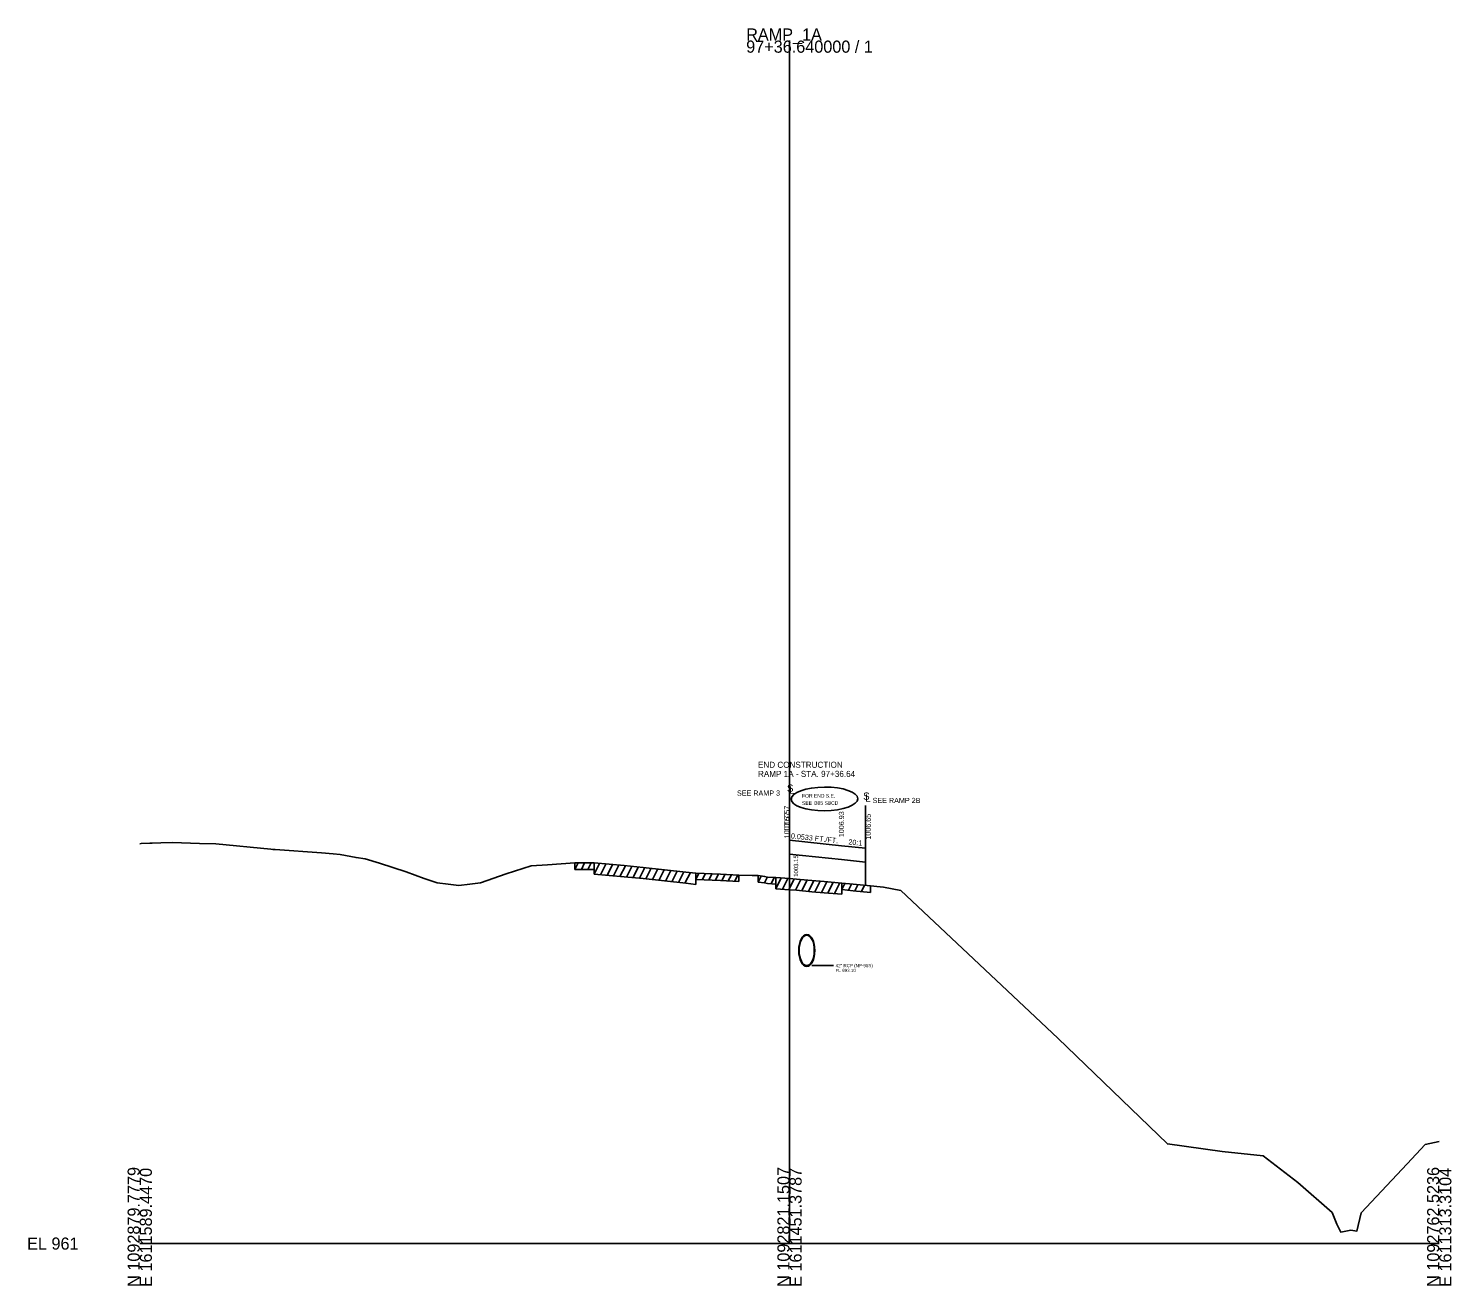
# Model space of a CAD drawing. Extents: x -26 to 1614341, y -10 to 1281970.
# Drawn here: x 1274.3 to 1602.8, y 6990.3 to 7280.6 of the extents above; entities that cross this region are included whole.
import ezdxf

# ---------------------------------------------------------------- set-up
doc = ezdxf.new("R2010")
doc.units = 0
for name, color, linetype in [('RD_EX_Misc', 7, 'Continuous'), ('RD_GPK_XS_Cell', 7, 'Continuous'), ('RD_PD_DR_Pipe', 7, 'Continuous'), ('RD_Sketch1', 7, 'Continuous'), ('RD_XS_Base', 7, 'Continuous'), ('RD_XS_ExGround', 7, 'Continuous'), ('RD_XS_ExPaveRet', 7, 'Continuous'), ('RD_XS_MatchLine', 7, 'Continuous'), ('RD_XS_Pave', 7, 'Continuous'), ('RD_XS_PaveShd', 7, 'Continuous'), ('RD_XS_Pipe', 7, 'Continuous'), ('RD_XS_TX_Elev_EX', 7, 'Continuous'), ('RD_XS_TX_Elev_PR', 7, 'Continuous'), ('RD_XS_TX_MatchLine', 7, 'Continuous'), ('RD_XS_TX_Notes', 7, 'Continuous'), ('RD_XS_TX_ShdSlope', 7, 'Continuous'), ('RD_XS_TX_Slope', 7, 'Continuous')]:
    doc.layers.add(name, color=color, linetype=linetype)

msp = doc.modelspace()

# ---------------------------------------------------------------- linework, layer by layer
at = {"layer": 'RD_EX_Misc'}
for p, q in [((1400.46, 7086.43), (1400.46, 7087.93)), ((1404.87, 7087.9), (1404.87, 7086.4)), ((1400.46, 7086.43), (1403.15, 7086.41)), ((1400.46, 7086.43), (1400.46, 7086.43)), ((1403.15, 7086.41), (1404.87, 7086.4)), ((1404.87, 7086.4), (1404.87, 7086.4)), ((1428.35, 7084.06), (1428.35, 7085.56)), ((1428.35, 7084.06), (1434.11, 7083.82)), ((1428.35, 7084.06), (1428.35, 7084.06)), ((1434.11, 7083.82), (1438.34, 7083.62)), ((1438.34, 7085.12), (1438.34, 7083.62)), ((1442.74, 7083.49), (1442.74, 7084.99)), ((1442.74, 7083.49), (1444.26, 7083.28)), ((1444.26, 7083.28), (1444.96, 7083.16)), ((1444.96, 7083.16), (1446.85, 7083.03)), ((1446.85, 7084.53), (1446.85, 7083.03)), ((1462.1, 7081.76), (1462.1, 7083.26)), ((1462.1, 7081.76), (1464.73, 7081.49)), ((1464.73, 7081.49), (1468.71, 7081.12)), ((1468.71, 7082.62), (1468.71, 7081.12))]:
    msp.add_line(p, q, dxfattribs=at)
at = {"layer": 'RD_GPK_XS_Cell'}
for p, q in [((1450, 7000), (1450, 7277.83)), ((1300, 7000), (1450, 7000)), ((1450, 7000), (1600, 7000))]:
    msp.add_line(p, q, dxfattribs=at)
at = {"layer": 'RD_PD_DR_Pipe'}
msp.add_line((1450, 7093.13), (1462, 7091.85), dxfattribs=at)
msp.add_line((1450, 7093.13), (1462, 7091.85), dxfattribs=at)
at = {"layer": 'RD_Sketch1'}
for p, q in [((1400.46, 7086.43), (1401.21, 7087.93)), ((1401.96, 7086.42), (1402.71, 7087.92)), ((1403.46, 7086.41), (1404.21, 7087.9)), ((1428.35, 7084.06), (1429.08, 7085.53)), ((1429.85, 7084), (1430.58, 7085.47)), ((1431.35, 7083.94), (1432.08, 7085.4)), ((1432.85, 7083.87), (1433.58, 7085.34)), ((1434.35, 7083.81), (1435.08, 7085.27)), ((1435.85, 7083.74), (1436.58, 7085.2)), ((1437.35, 7083.67), (1438.08, 7085.13)), ((1442.74, 7083.49), (1443.44, 7084.89)), ((1444.24, 7083.28), (1444.93, 7084.67)), ((1445.74, 7083.11), (1446.46, 7084.55)), ((1462.1, 7081.76), (1462.81, 7083.19)), ((1463.6, 7081.61), (1464.31, 7083.03)), ((1465.1, 7081.45), (1465.81, 7082.89)), ((1466.6, 7081.31), (1467.31, 7082.75))]:
    msp.add_line(p, q, dxfattribs=at)
at = {"layer": 'RD_XS_Base'}
for p, q in [((1450, 7089.97), (1462, 7088.69)), ((1462, 7088.69), (1467.58, 7088.12))]:
    msp.add_line(p, q, dxfattribs=at)
at = {"layer": 'RD_XS_ExGround'}
msp.add_lwpolyline([(1300, 7092.35), (1300.32, 7092.37), (1302.29, 7092.48), (1302.84, 7092.51), (1304.86, 7092.56), (1307.53, 7092.61), (1313.77, 7092.4), (1317.55, 7092.34), (1330.28, 7091.09), (1330.76, 7091.04), (1331.23, 7091.01), (1341.94, 7090.24), (1344.65, 7090.03), (1346.25, 7089.88), (1349.94, 7089.15), (1352.06, 7088.84), (1355.32, 7087.84), (1361.5, 7085.82), (1365.68, 7084.35), (1368.63, 7083.28), (1371.17, 7082.98), (1373.63, 7082.68), (1376.21, 7082.99), (1378.63, 7083.29), (1384.57, 7085.37), (1390.35, 7087.27), (1394.16, 7087.48), (1400.46, 7087.93), (1403.15, 7087.91), (1404.87, 7087.9), (1411.81, 7087.29), (1416.23, 7086.89), (1426.04, 7085.8), (1428.35, 7085.56), (1434.11, 7085.32), (1438.34, 7085.12), (1441.36, 7085), (1442.74, 7084.99), (1444.26, 7084.78), (1444.96, 7084.66), (1446.86, 7084.53), (1450, 7084.3), (1451.6, 7084.19), (1455.13, 7083.87), (1458.02, 7083.63), (1462.1, 7083.26), (1464.73, 7082.99), (1468.72, 7082.62), (1470.91, 7082.39), (1471.69, 7082.3), (1475.71, 7081.51), (1511.98, 7047.46), (1537.23, 7023.01), (1549.86, 7021.23), (1559.39, 7020.25), (1567.36, 7014.1), (1575.27, 7007.16), (1576.34, 7004.49), (1577.26, 7002.66), (1579.59, 7003.06), (1581.01, 7002.87), (1581.98, 7007.07), (1592.63, 7018.44), (1596.74, 7022.87), (1600, 7023.54)], dxfattribs=at)
at = {"layer": 'RD_XS_ExPaveRet'}
for p, q in [((1404.87, 7085.3), (1404.87, 7087.9)), ((1404.87, 7085.3), (1406.11, 7087.79)), ((1406.37, 7085.17), (1407.61, 7087.66)), ((1407.87, 7085.04), (1409.11, 7087.53)), ((1409.37, 7084.9), (1410.61, 7087.39)), ((1410.87, 7084.77), (1412.11, 7087.26)), ((1412.37, 7084.64), (1413.61, 7087.12)), ((1413.87, 7084.5), (1415.11, 7086.99)), ((1415.37, 7084.36), (1416.61, 7086.84)), ((1416.87, 7084.22), (1418.1, 7086.68)), ((1418.37, 7084.05), (1419.6, 7086.51)), ((1404.87, 7085.3), (1411.81, 7084.69)), ((1411.81, 7084.69), (1416.23, 7084.29)), ((1416.23, 7084.29), (1426.04, 7083.2)), ((1419.87, 7083.88), (1421.1, 7086.35)), ((1421.37, 7083.72), (1422.6, 7086.18)), ((1422.87, 7083.55), (1424.1, 7086.02)), ((1424.37, 7083.39), (1425.6, 7085.85)), ((1425.87, 7083.22), (1427.11, 7085.69)), ((1426.04, 7083.2), (1428.35, 7082.96)), ((1428.35, 7085.56), (1428.35, 7082.96)), ((1446.85, 7081.93), (1446.85, 7084.53)), ((1446.85, 7081.93), (1448.11, 7084.44)), ((1448.35, 7081.82), (1449.61, 7084.33)), ((1449.85, 7081.71), (1451.11, 7084.23)), ((1451.35, 7081.61), (1452.6, 7084.1)), ((1452.85, 7081.48), (1454.1, 7083.97)), ((1454.36, 7081.34), (1455.6, 7083.83)), ((1455.86, 7081.21), (1457.1, 7083.71)), ((1457.36, 7081.08), (1458.6, 7083.58)), ((1458.86, 7080.95), (1460.1, 7083.44)), ((1460.36, 7080.82), (1461.6, 7083.31)), ((1462.1, 7083.26), (1462.1, 7080.66)), ((1446.85, 7081.93), (1446.86, 7081.93)), ((1446.86, 7081.93), (1450, 7081.7)), ((1450, 7081.7), (1451.6, 7081.59)), ((1451.6, 7081.59), (1455.13, 7081.27)), ((1455.13, 7081.27), (1458.02, 7081.03)), ((1458.02, 7081.03), (1462.1, 7080.66))]:
    msp.add_line(p, q, dxfattribs=at)
at = {"layer": 'RD_XS_MatchLine'}
for p, q in [((1450, 7084.3), (1450, 7093.13)), ((1467.58, 7082.72), (1467.58, 7091.29))]:
    msp.add_line(p, q, dxfattribs=at)
at = {"layer": 'RD_XS_Pave'}
msp.add_line((1450, 7093.13), (1462, 7091.85), dxfattribs=at)
at = {"layer": 'RD_XS_PaveShd'}
msp.add_line((1462, 7091.85), (1467.58, 7091.29), dxfattribs=at)
at = {"layer": 'RD_XS_Pipe'}
msp.add_line((1455.15, 7064.2), (1460.15, 7064.2), dxfattribs=at)
for major_axis in [(0, 3.7), (0, 3.5)]:
    msp.add_ellipse((1453.98, 7067.7), major_axis=major_axis, ratio=0.5, dxfattribs=at)
at = {"layer": 'RD_XS_TX_MatchLine'}
for p, q in [((1450, 7093.13), (1450, 7103.02)), ((1467.58, 7091.29), (1467.58, 7101.18)), ((1450, 7088.13), (1450, 7093.13)), ((1467.58, 7086.29), (1467.58, 7091.29))]:
    msp.add_line(p, q, dxfattribs=at)
at = {"layer": 'RD_XS_TX_Notes'}
msp.add_ellipse((1458.08, 7102.7), major_axis=(7.68, 0.05), ratio=0.355189, dxfattribs=at)

# ---------------------------------------------------------------- texts
at = {"layer": 'RD_GPK_XS_Cell'}
for s, p in [('RAMP_1A', (1440, 7277.83)), ('97+36.640000 / 1', (1440, 7275.03)), ('EL 961', (1274, 6998.6))]:
    msp.add_text(s, height=2.8, dxfattribs=at).set_placement(p)
for s, p in [('N 1092879.7779', (1300, 6990)), ('N 1092821.1507', (1450, 6990)), ('N 1092762.5236', (1600, 6990)), ('E 1611589.4470', (1302.8, 6990)), ('E 1611451.3787', (1452.8, 6990)), ('E 1611313.3104', (1602.8, 6990))]:
    msp.add_text(s, height=2.8, rotation=90, dxfattribs=at).set_placement(p)
at = {"layer": 'RD_PD_DR_Pipe'}
msp.add_text(' 1007.57', height=1.2, rotation=90, dxfattribs=at).set_placement((1450, 7093.13))
msp.add_text(' 1007.57', height=1.2, rotation=90, dxfattribs=at).set_placement((1450, 7093.13))
at = {"layer": 'RD_XS_Pipe'}
for s, p in [('42" RCP (NP-95S)', (1460.65, 7063.83)), ('FL 993.10', (1460.65, 7062.7))]:
    msp.add_text(s, height=0.75, dxfattribs=at).set_placement(p)
at = {"layer": 'RD_XS_TX_Elev_EX'}
msp.add_text('1003.15', height=1, rotation=90, dxfattribs=at).set_placement((1452, 7084.7))
at = {"layer": 'RD_XS_TX_Elev_PR'}
for s, p in [('1007.57', (1450, 7095.13)), ('1006.93', (1462.6, 7093.85)), ('1006.65', (1468.78, 7093.29))]:
    msp.add_text(s, height=1.2, rotation=90, dxfattribs=at).set_placement(p)
at = {"layer": 'RD_XS_TX_MatchLine'}
for s, p in [('S', (1449.42, 7104.34)), ('L', (1449.93, 7103.9)), ('S', (1467, 7102.49)), ('L', (1467.51, 7102.06))]:
    msp.add_text(s, height=1.68, dxfattribs=at).set_placement(p)
at = {"layer": 'RD_XS_TX_Notes'}
for s, height, p in [('END CONSTRUCTION', 1.4, (1442.73, 7109.88)), ('RAMP 1A - STA. 97+36.64', 1.4, (1442.73, 7107.78)), ('FOR END S.E.', 0.8333, (1452.9, 7102.99)), ('SEE I385 SBCD', 0.8333, (1452.9, 7101.32))]:
    msp.add_text(s, height=height, dxfattribs=at).set_placement(p)
for s, p in [('SEE RAMP 3', (1437.87, 7103.44)), ('SEE RAMP 2B', (1469.18, 7101.74))]:
    msp.add_text(s, height=1.2, rotation=360, dxfattribs=at).set_placement(p)
at = {"layer": 'RD_XS_TX_ShdSlope'}
msp.add_text('20:1', height=1.2, rotation=354.2379, dxfattribs=at).set_placement((1463.55, 7092.2))
at = {"layer": 'RD_XS_TX_Slope'}
msp.add_text('0.0533 FT./FT.', height=1.2, rotation=353.9115, dxfattribs=at).set_placement((1450.28, 7093.6))

doc.saveas('drawing.dxf')
